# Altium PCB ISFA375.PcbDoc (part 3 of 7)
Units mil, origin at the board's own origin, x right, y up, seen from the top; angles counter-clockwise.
Board outline 5615 x 5520 mil, 6 copper layers (Top_SL, GND, POWER, Signal_Layer, GND2, Bottom_SL), stack 60.472 mil thick; 494 components, 307 nets, 1648 pads, 755 vias.
Unrouted connection lines stored in the file: 315.
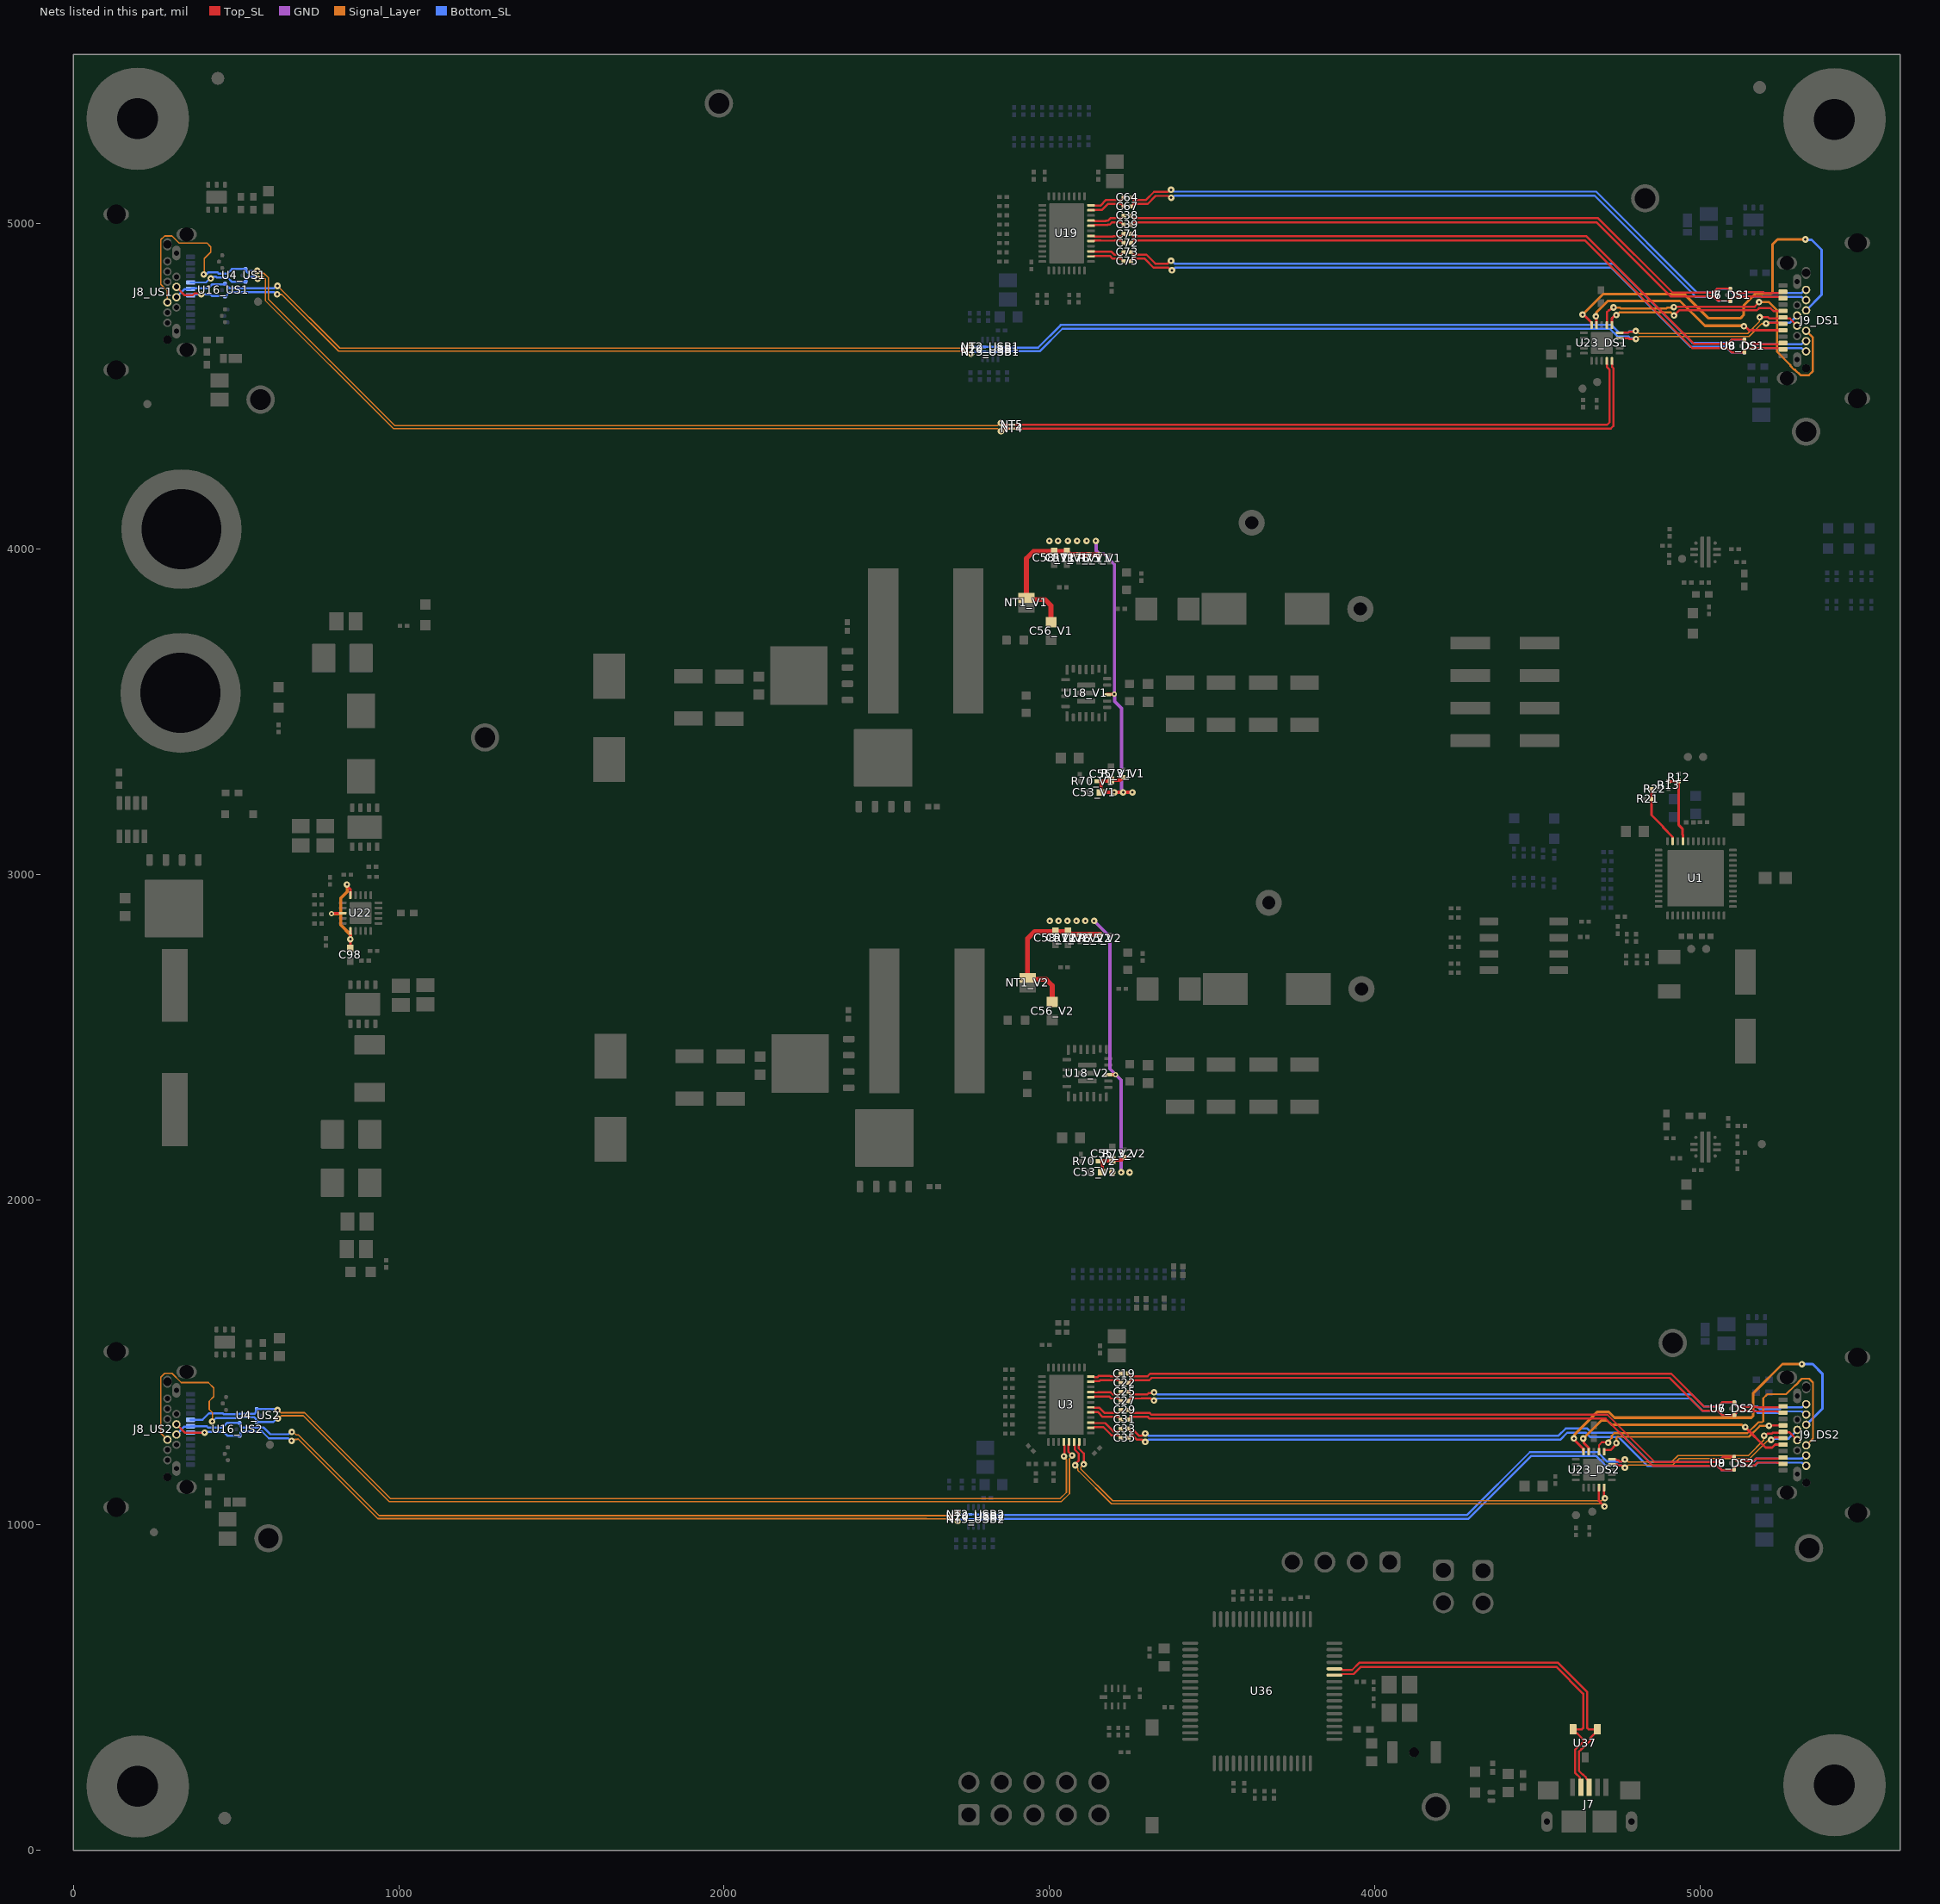
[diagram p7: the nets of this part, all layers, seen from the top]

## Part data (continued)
R114: library part CMP-0027444-1, "RES, 1.69 k, 1%, 0.05 W, 0201", Manufacturer="Yageo America", Power_W=50mW, Supplier Part Number 1=YAG2487CT-ND, TempCo="200 ppm/C", Tolerance_%=1%, Value2=0.05W, Value_Code=1k69, ValueDisplayed=1.69k
R115 R134: library part CMP-0027857-1, "RES, 715, 1%, 0.05 W, 0201", Manufacturer="Yageo America", Power_W=50mW, Supplier Part Number 1=YAG2786CT-ND, TempCo="200 ppm/C", Tolerance_%=1%, Value2=0.05W, Value_Code=715R, ValueDisplayed=715
R117_V1 R117_V2: library part CMP-0027696-1, "RES, 42.2 k, 1%, 0.05 W, 0201", Manufacturer="Yageo America", Power_W=50mW, Supplier Part Number 1=YAG2666CT-ND, TempCo="200 ppm/C", Tolerance_%=1%, Value2=0.05W, Value_Code=42k2, ValueDisplayed=42.2k
R127: library part CMP-0026825-5, "RES, 10 k, 5%, 0.063 W, AEC-Q200 Grade 0, 0402", Manufacturer=Vishay-Dale, Power_W=63mW, Supplier Part Number 1=541-10KJCT-ND, TempCo="200 ppm/C", Tolerance_%=5%, Value2=0.063W, Value_Code=10k0, ValueDisplayed=10k
R163_DS1 R163_DS2: library part CMP-0027261-3, "RES, 100 k, 1%, 0.05 W, 0201", Manufacturer=Vishay-Dale, Power_W=50mW, Supplier Part Number 1=541-100KAABCT-ND, TempCo="100 ppm/C", Tolerance_%=1%, Value2=0.05W, Value_Code=100k
R164 R172: library part CMP-0083836-1, "RES, 100, 1%, 0.05 W, 0201", Manufacturer=Vishay-Semiconductor, Power_W=50mW, TempCo="100 ppm/C", Tolerance_%=1%, Value2=0.05W, Value_Code=100R, ValueDisplayed=100
S1: library part CMP-0002163-2, "Switch, Slide, SPST, Top Slide, SMT", CurrentRating_mA=100A, Manufacturer="Copal Electronics", Supplier Part Number 1=563-1004-1-ND
S4: library part CMP-0095173-1, "Tactile Switch SPST-NO Top Actuated Surface Mount", Coil Resistance_ohm=100mΩ, Contact Current Rating=50mA, Digikey Part Number=SW1143CT-ND, Manufacturer=Omron, Mouser Part Number=653-B3U-1000P-B, Operating Force=1.5N, Operating Temperature Range="-25°C to +70°C"
TP1 TP2 TP4 TP5 TP13_DS1 TP13_DS2 TP14_DS1 TP14_DS2 TP15 TP16 TP17_US1 TP17_US2 TP18_US1 TP18_US2: library part CMP-0078143-3, "TEST POINT.  No entry in BOM.", Manufacturer=N/A
TP6 TP9_US1 TP9_US2 TP10_DS1 TP10_DS2 TP12 TP19: library part CMP-0055142-1, "Test Point, Compact, Red, TH", Color=Red, Manufacturer=Keystone, Supplier Part Number 1=36-5005-ND
TP7_V1 TP7_V2 TP8_V1 TP8_V2: library part CMP-0055140-1, "Test Point, Miniature, Orange, TH", Color=Orange, Manufacturer=Keystone, Supplier Part Number 1=36-5003-ND
TP11_DS1 TP11_DS2: library part CMP-0055143-2, "Test Point, Compact, Black, TH", Color=Black, Manufacturer="Keystone Electronics", Supplier Part Number 1=36-5006-ND
U1: library part CMP-0088521-10, "Dual Port USB Type-C and USB PD Controller with Integrated Source Power Switches", Manufacturer="Texas instruments", Max Supply Voltage=22V, Min Supply Voltage=0V, Operating Temperature Range="-10°C to +125°C"
U2: library part CMP-0005313-2, "256 kb I2C CMOS Serial EEPROM, SOIC-8", Manufacturer="ON Semiconductor", Supplier Part Number 1=CAT24C256WI-GT3OSCT-ND
U3: library part CMP-0082004-1, "USB TYPE-C(TM) 10 Gbps Multi-Protocol Bi-Directional Linear Redriver, RNQ0040A (WQFN-40)", Alternate Manufacturer="Texas Instruments", Alternate PartNumber=TUSB1044IRNQR, Operating Temperature Range="-40 to 85"
U4_US1 U4_US2 U6_DS1 U6_DS2 U7_DS1 U7_DS2 U8_DS1 U8_DS2 U9_DS1 U9_DS2 U12_US1 U12_US2 U13_US1 U13_US2 U14_US1 U14_US2 U15_US1 U15_US2 U16_US1 U16_US2: library part CMP-0013358-2, "2-Channel ESD Protection Diode for USB Type-C and HDMI 2.0, DMY0003A (X1SON-3)", Alternate Manufacturer="Texas Instruments"
U5: library part CMP-0091365-1, "Low IQ Reverse Battery Protection Controller, SOT23-8", Manufacturer="Texas Instruments", Max Supply Voltage=60V, Min Supply Voltage=4V, Nominal Supply Current=80uA, Operating Temperature Range="-40°C to +150°C"
U10 U25: library part CMP-0088339-1, "2.7- 23V, 5.5 A Integrated Ideal Diode Power Switch with Input Reverse Polarity and Overvoltage Protection", Manufacturer="Texas Instruments", Max Supply Voltage=23V, Min Supply Voltage=2.7V, Nominal Supply Current=230uA, Operating Temperature Range="-40°C to +125°C", Output Voltage=42V
U11: library part CMP-0033716-1, "High-Speed USB 2.0 (480 Mbps) 1:2 Multiplexer / Demultiplexer Switch with Single Enable, 6 ohm RON, 2.5 to 3.3V, -40 to 85 degC, 10-Pin UQFN (RSE), Green (RoHS & no Sb/Br)", Manufacturer="Texas Instruments"
U18_V1 U18_V2: library part CMP-0861085-2, "36-V, 16-A Buck-Boost Converter, RPM0026A (VQFN-HR-26)", Alternate Manufacturer="Texas Instruments"
U19: library part CMP-0092691-1, "USB Type-C 10Gbps USB3.2 x2 Adaptive Linear Redriver", Manufacturer="Texas Instruments", Max Supply Voltage=3.6V, Min Supply Voltage=1.7V, Operating Temperature Range="0°C to +70°C"
U20_USB1 U20_USB2: library part CMP-0093449-1, "USB 2.0 high-speed signal conditioner with BC 1.2 controller 12-X2QFN -40 to 85", Manufacturer="Texas Instruments", Max Supply Voltage=6.5V, Min Supply Voltage=2.3V, Mouser Part Number=595-TUSB216IRWBT, Nominal Supply Current=0.75-22mA, Operating Temperature Range="-40°C to +85°C"
U21_DS1 U21_DS2 U24_US1 U24_US2: library part CMP-0077834-1, "22-V Precision Surge Protection Clamp, DRV0006A (WSON-6)", Alternate Manufacturer="Texas Instruments"
U22: library part CMP-0081825-1, "Dual Synchronous Step-Down Controller with 5-V and 3.3-V LDOs, RUK0020B (WQFN-20)", Alternate Manufacturer="Texas Instruments", Alternate PartNumber=TPS51225RUKR, Operating Temperature Range="-40 to 85 C", Rating=Catalog
U23_DS1 U23_DS2: library part CMP-0081565-1, "USB Type-C Port Protector: Short-to-VBUS Overvoltage and IEC ESD Protection, RUK0020B (WQFN-20)", Alternate Manufacturer="Texas Instruments"
U36: library part CMP-0029860-3, "Tiva C Series Microcontroller, 256 KB Flash, 32 KB SRAM, 12 Bit, 12 Channels, -40 to 105 degC, 64-Pin LQFP (PM), Green (RoHS & no Sb/Br), Tape and Reel", Manufacturer="Texas Instruments", Temperature Range="-40 to 105 degC"
U37: library part CMP-0043101-1, "ESD Protection Array for High-Speed Data Interfaces, 2 Channels, -40 to +85 degC, 3-pin SOT-23 (DBZ), Green (RoHS & no Sb/Br)", Breakdown Voltage(Min)(V)=9, Differential Capacitance(pF)=0.01, IO Capacitance(Typ)(pF)=0.7, IO Leakage Current(nA)=10, Manufacturer="Texas Instruments"
Y1: library part CMP-0004635-3, "Crystal, 16 MHz, 8pF, SMD", Frequency Stability=+/-30ppm, Frequency_Fixed=16MHz, Manufacturer=NDK, Supplier Part Number 1=644-1157-1-ND

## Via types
v1: diameter 20, hole 8, Top_SL to Bottom_SL, 628 vias
v2: diameter 19.68, hole 7.87, Top_SL to Bottom_SL, 66 vias
v3: diameter 16, hole 8, Top_SL to Bottom_SL, 23 vias
v4: diameter 16, hole 6, Top_SL to Bottom_SL, tented both sides, 16 vias
v5: diameter 137.8, hole 125.98, Top_SL to Bottom_SL, 8 vias
v6: diameter 50, hole 28, Top_SL to Bottom_SL, 8 vias
v7: diameter 28, hole 16, Top_SL to Bottom_SL, 6 vias

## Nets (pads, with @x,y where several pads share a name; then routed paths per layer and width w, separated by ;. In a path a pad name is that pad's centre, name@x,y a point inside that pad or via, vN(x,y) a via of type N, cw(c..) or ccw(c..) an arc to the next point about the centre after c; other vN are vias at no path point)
3V3_LDO_EN: C98.1 U22.3 U22.6 U22.20 | length 340.7
  Top_SL w8: v3(792.61,2879.44) 793.36,2880.19 826.6,2880.19 U22.3@827.35,2880.95 ; v1(840.21,2968.87) 840.21,2965.62 851.04,2954.79 U22.20@850.98,2936.06 U22.20@850.98,2936.06 ; C98.1@850.16,2776.43 850.89,2777.16 850.89,2800.31 v1(851.22,2800.64) 851.1,2800.76 851.1,2825.71 U22.6@850.98,2825.83
  Signal_Layer w10: v3(792.61,2879.44) 821.45,2879.44 ; v1(840.21,2968.87) 841.3,2967.77 841.3,2946.86 821.45,2927.01 821.45,2879.44 ; v1(851.22,2800.64) 851.22,2814.76 821.45,2844.53 821.45,2879.44
ADCIN1: R12.2 R13.1 U1.33 | length 222.4
  Top_SL w8: R13.1@4903.32,3285.62 4933.62,3285.62 R12.2@4934.92,3286.92 ; R12.2@4934.92,3287.2 R12.2@4934.92,3286.92 ; U1.33@4947.63,3102.17 U1.33@4947.63,3102.17 4947.57,3121.23 4945.78,3123.01 4945.78,3140.48 4934.92,3151.34 R12.2@4934.92,3286.92
ADCIN2: R21.2 R22.1 U1.35 | length 187.2
  Top_SL w8: R22.1@4849.98,3262 4850.43,3261.55 4850.43,3232.01 R21.2@4850.88,3231.56 4850.88,3182.11 4886.5,3146.5 4886.5,3144.61 4916.07,3115.04 U1.35@4916.13,3102.17 U1.35@4916.13,3102.17
AGND_V1: C53_V1.2 C55_V1.1 C56_V1.2 C57_V1.2 C58_V1.2 NT1_V1.2 R70_V1.1 R73_V1.1 R75_V1.1 R76_V1.1 R117_V1.1 U18_V1.10 | length 1553.3
  Top_SL w10: R76_V1.1@3122.27,3982.39 R76_V1.1@3123.57,3983.69 ; R70_V1.1@3145.42,3285.96 3146.72,3287.26 3158.89,3287.26 ; C53_V1.2@3156.81,3252.17 C53_V1.2@3161.42,3252.17 ; U18_V1.10@3176.16,3553.74 v3(3199.63,3553.74) ; R73_V1.1@3226.92,3297.6 3218.66,3289.34 3189.99,3289.34 C55_V1.1@3189.63,3289.7 3187.19,3287.26 3158.89,3287.26 ; v1(3255.01,3252.17) v1(3226.85,3252.17) v1(3199.31,3252.17) C53_V1.2@3161.42,3252.17 ; 3158.89,3287.26 3158.89,3254.7 C53_V1.2@3161.42,3252.17
  Top_SL w15: C56_V1.2@3004.92,3775.56 3004.92,3826.39 2986.31,3845 2934.19,3845 NT1_V1.2@2929.19,3850 2929.19,3971 2950.76,3992.57 C58_V1.2@3014.74,3992.57 C57_V1.2@3053.74,3992.57 3062.54,3983.77 3089.37,3983.77 R76_V1.1@3122.27,3983.77 ; R76_V1.1@3122.27,3982.39 R75_V1.1@3152.39,3982.39
  GND w10: v1(3142.86,4025.35) 3144.02,4024.19 3144.02,3995.35 3154.34,3985.02 3168.09,3985.02 3199.63,3953.49 v3(3199.63,3553.74) 3200.78,3552.59 3200.78,3531.75 3221.67,3510.86 v1@3221.67,3252.17
  other v1: 2999.63,4025.35 3026.55,4025.35 3056.76,4025.35 3085,4025 3114,4025
AGND_V2: C53_V2.2 C55_V2.1 C56_V2.2 C57_V2.2 C58_V2.2 NT1_V2.2 R70_V2.1 R73_V2.1 R75_V2.1 R76_V2.1 R117_V2.1 U18_V2.10 | length 1446.7
  Top_SL w10: R70_V2.1@3149.2,2117.96 3150.5,2119.26 3162.67,2119.26 ; C53_V2.2@3165.21,2083.88 3165.21,2084.17 3162.67,2086.7 3162.67,2119.26 ; U18_V2.10@3181.12,2384.43 3181.19,2384.51 3203.18,2384.51 v3(3203.42,2384.75) ; R73_V2.1@3230.71,2129.6 3222.45,2121.34 3193.78,2121.34 C55_V2.1@3193.42,2121.7 3190.98,2119.26 3162.67,2119.26
  Top_SL w15: C56_V2.2@3008.71,2607.56 3008.71,2658.39 2990.09,2677 2937.98,2677 NT1_V2.2@2932.98,2682 2932.98,2803 2954.54,2824.57 C58_V2.2@3018.53,2824.57 C57_V2.2@3057.53,2824.57 3066.33,2815.77 R75_V2.1@3156.5,2815.77
  GND w10: v1(3137.18,2857.35) 3185.91,2808.61 3185.91,2402.25 v3(3203.42,2384.75) 3220.61,2367.56 v1(3220.61,2084.17)
  other v1: 3193.78,2083.88 3246.41,2083.88 3001,2857 3028,2857 3055.62,2857.35 3083,2857 3110.4,2857.29
AUX_DS1_N: NT5.2 U23_DS1.14 | length 2027.3
  Top_SL w6.5: NT5.2@2890.19,4381.81 2904,4381.81 4714.16,4381.81 4722.5,4390.16 4722.5,4550.85 4714.4,4558.96 4714.4,4577.36 U23_DS1.14@4713.72,4578.05
AUX_DS1_P: NT4.2 U23_DS1.15 | length 2048.7
  Top_SL w6.5: NT4.2@2889,4370 4724.66,4370.31 ; 4725.66,4370.31 4734,4378.66 4734,4555.62 4730.15,4559.47 4730.15,4577.36 U23_DS1.15@4729.46,4578.05
AUX_DS2_N: U3.26 U23_DS2.14 | length 1831.4
  Top_SL w6.5: U3.26@3075.86,1255.56 3076.55,1254.88 3076.55,1244.88 3078.05,1243.38 3078.05,1231.47 3090.46,1219.06 3090.46,1198.86 3079.17,1187.57 v1(3079.17,1183.91) ; U23_DS2.14@4689.43,1115.2 4689.43,1074.01 v1(4706.28,1057.15)
  Signal_Layer w4.32: v1(3079.17,1183.91) 3079.17,1181.99 3087.61,1173.54 3087.61,1168 3090.53,1165.07 3190.39,1065.21 4695.91,1065.21 4703.98,1057.15 v1(4706.28,1057.15)
AUX_DS2_P: U3.27 U23_DS2.15 | length 1783.2
  Top_SL w6.5: U3.27@3091.61,1255.56 3091.61,1247.69 3089.55,1245.63 3089.55,1236.23 3105.66,1220.12 v1(3105.66,1187.06) ; U23_DS2.15@4705.17,1115.2 4705.17,1084.61 v1(4707.68,1082.11)
  Signal_Layer w4.32: v1(3105.66,1187.06) 3105.66,1186.68 3096.93,1177.95 3096.93,1171.86 3194.25,1074.53 4697.3,1074.53 4704.88,1082.11 v1(4707.68,1082.11)
AUX_US1_N: J8_US1.B8 NT5.1 U4_US1.2@528.92,4860.69 | length 3205.7
  Top_SL w6.5: v1(2851.11,4387.78) 2854.76,4387.78 2860.73,4381.81 NT5.1@2879.81,4381.81
  Signal_Layer w4.32: J8_US1.B8@288.66,4758.5 288.66,4793.28 268.71,4813.23 268.71,4950.82 280.4,4962.51 302.59,4962.51 324.79,4940.32 410.49,4940.32 421.76,4929.04 421.76,4912.49 401.94,4892.67 401.94,4846.17 v1(400.2,4844.43) ; v1(565.27,4855.26) 568.65,4855.26 575.55,4848.35 584.51,4848.35 598.87,4833.99 598.87,4768.02 986.95,4379.94 2840.74,4379.94 2848.58,4387.78 v1(2851.11,4387.78)
  Bottom_SL w6.5: v1(400.2,4844.43) 402.79,4847.01 410.92,4847.01 414.21,4850.31 442.77,4850.31 445.83,4847.25 473.63,4847.25 487.07,4860.69 U4_US1.2@528.92,4860.69 531.14,4858.47 531.14,4853.82 535.38,4849.58 541.07,4855.26 v1(565.27,4855.26)
AUX_US1_P: J8_US1.A8 NT4.1 U4_US1.3@528.92,4821.32 | length 2790.7
  Top_SL w6.5: v1@2851,4363 2854.98,4363 2861.98,4370 NT4.1@2880,4370
  Signal_Layer w4.32: v1(565.6,4830.26) 566.78,4830.26 575.55,4839.03 580.65,4839.03 589.55,4830.13 589.55,4764.16 983.09,4370.62 2840.74,4370.62 2848.58,4362.78 v1(2851.11,4362.78)
  Bottom_SL w6.5: J8_US1.A8@359.92,4819.53 407.33,4819.53 416.43,4828.63 418.53,4828.63 v1(421.89,4831.99) ; v1@421.77,4832.06 425.42,4832.06 431.05,4837.69 437.71,4837.69 440.65,4834.75 473.63,4834.75 487.07,4821.32 U4_US1.3@528.92,4821.32 531.14,4823.53 531.14,4830.94 537.27,4837.08 555.65,4837.08 562.46,4830.26 v1(565.6,4830.26)
AUX_US2_N: J8_US2.B8 U3.25 U4_US2.2@562.87,1316.9 | length 3445.2
  Top_SL w6.5: U3.25@3060.11,1255.56 3060.11,1247.69 3058.05,1245.63 3058.05,1225.94 3069.67,1214.32 v1(3069.67,1214.04)
  Signal_Layer w4.32: J8_US2.B8@288.66,1262.5 268.71,1282.46 268.71,1454.82 280.4,1466.51 302.59,1466.51 331.16,1437.94 414.58,1437.94 431.34,1421.19 431.34,1395.01 417.19,1380.86 417.19,1355.28 427.24,1345.23 427.24,1319.62 v1(426.2,1318.58) ; v1(628.61,1327.9) 630.93,1327.9 639.02,1335.99 706.4,1335.99 969.97,1072.42 3037.34,1072.42 3061.56,1096.64 3061.56,1203.67 3069.67,1211.78 v1(3069.67,1214.04)
  Bottom_SL w6.5: v1(426.2,1318.58) 427.63,1318.58 437.71,1328.66 512.52,1328.66 514.69,1330.83 555.86,1330.83 561.19,1325.5 561.19,1318.58 U4_US2.2@562.87,1316.9 613.95,1316.9 624.96,1327.9 v1(628.61,1327.9)
AUX_US2_P: J8_US2.A8 U3.24 U4_US2.3@562.87,1356.27 | length 2986.8
  Top_SL w6.5: U3.24@3044.36,1255.56 3045.05,1254.88 3045.05,1244.88 3046.55,1243.38 3046.55,1222 3045.78,1221.23 3045.78,1212.42 v1(3044.8,1211.44)
  Signal_Layer w4.32: v1(627.45,1353.45) 629.71,1353.45 637.84,1345.31 710.26,1345.31 973.83,1081.74 3033.48,1081.74 3052.24,1100.5 3052.24,1201.07 3044.8,1208.5 v1(3044.8,1211.44)
  Bottom_SL w6.5: J8_US2.A8@359.92,1323.53 396.24,1323.53 416.05,1343.33 458.74,1343.33 461.92,1340.16 507.76,1340.16 509.93,1342.33 556.85,1342.33 560.65,1346.14 560.65,1354.05 U4_US2.3@562.87,1356.27 v1@620.98,1356.27
C_AUX_DS1_N: J9_DS1.B8 U23_DS1.2 | length 995.3
  Top_SL w6.5: U23_DS1.2@4713.72,4688.49 4713.72,4728.21 4719.44,4733.94 4721.58,4733.94 4730.35,4742.72 v1(4734,4742.72) ; v1(4919.2,4743.9) 4920.55,4745.25 5167.96,4745.25 v1(5181.54,4758.83)
  Signal_Layer w6.5: v1(4734,4742.72) 4734.25,4742.47 4753.75,4742.47 4757,4739.22 4896.2,4739.22 4899.45,4742.47 4917.77,4742.47 v1(4919.2,4743.9) ; v1(5181.54,4758.83) 5211.93,4758.83 5237.01,4733.75 5237.01,4606.53 5277.56,4565.97 5277.56,4563.63 5289.89,4551.3 5292.23,4551.3 5308.96,4534.57 5334.89,4534.57 5347.21,4546.9 5347.21,4649.73 J9_DS1.B8@5326.17,4670.77
C_AUX_DS1_P: J9_DS1.A8 U23_DS1.1 | length 563.7
  Top_SL w6.5: v1(4920.07,4717.75) 4936.07,4733.75 5174.71,4733.75 5181.54,4740.58 5217.09,4740.58 5225.87,4731.8 J9_DS1.A8@5254.91,4731.8
  Top_SL w8: U23_DS1.1@4729.53,4696.3 4729.53,4710.13 4731.7,4712.3 4732.55,4712.3 4739.57,4719.32 v1(4742.82,4719.32)
  Signal_Layer w6.5: v1(4742.82,4719.32) 4744.42,4719.32 4752.82,4727.72 4908.97,4727.72 4918.94,4717.75 v1(4920.07,4717.75)
C_AUX_DS2_N: J9_DS2.B8 U23_DS2.2 | length 1017.6
  Top_SL w6: U23_DS2.2@4689.43,1225.44 4689.43,1245.64 4698.23,1254.44 4716.05,1254.44 v1(4717.68,1252.81)
  Signal_Layer w6: v1(4717.68,1252.81) 4717.68,1256.6 4728.84,1267.76 4728.84,1274.5 4736.6,1282.25 5145.66,1282.25 5179.65,1316.23 5190.67,1316.23 5194.19,1319.75 5194.19,1389.37 5206.82,1402 5264.86,1402 5292.43,1429.58 ccw(c5279.27,1453.93) 5303.62,1440.76 5312.98,1450.12 5335.13,1450.12 5347.31,1437.94 5347.31,1266.06 J9_DS2.B8@5326.51,1245.27
C_AUX_DS2_P: J9_DS2.A8 U23_DS2.1 | length 597.7
  Top_SL w6.5: U23_DS2.1@4705.17,1225.44 4705.17,1229.56 4705.86,1230.25 4725.34,1230.25 4733.23,1238.14 4733.23,1238.94 4742.67,1248.38 v1(4742.67,1252.03) ; v1(5212.19,1305.23) 5212.71,1305.76 5254.72,1305.76 J9_DS2.A8@5255.25,1306.29
  Signal_Layer w6: v1(4742.67,1252.03) 4742.87,1252.23 4742.87,1267.74 4746.38,1271.25 5150.22,1271.25 5184.2,1305.23 v1(5212.19,1305.23)
C_CC1_DS1: J9_DS1.A5 U23_DS1.4 | length 666.5
  Top_SL w8: v1(4679.72,4715.3) 4681.28,4713.74 4681.28,4689.22 U23_DS1.4@4682.22,4688.29 ; v1(5134.9,4684.76) 5137.2,4682.46 5140.99,4682.46 5150.7,4672.74 J9_DS1.A5@5254.91,4672.74
  Signal_Layer w8: v1(4679.72,4715.3) 4681.94,4717.53 4681.94,4728.19 4716.66,4762.9 4938.58,4762.9 5014.96,4686.52 5133.14,4686.52 v1(5134.9,4684.76)
C_CC1_DS2: J9_DS2.A5 U23_DS2.4 | length 723.1
  Top_SL w8: v1(4641.13,1265.94) 4642.89,1264.18 4642.89,1252.59 4647.1,1248.38 4647.1,1248.19 4657.93,1237.36 U23_DS2.4@4657.93,1225.44 ; v1(5139,1301.04) 5201.91,1238.14 5221.65,1238.14 5230.75,1247.24 J9_DS2.A5@5255.25,1247.24
  Signal_Layer w8: v1(4641.13,1265.94) 4696.94,1321.75 4714.78,1321.75 4728.53,1308 5128.48,1308 5135.44,1301.04 v1(5139,1301.04)
C_CC2_DS1: J9_DS1.B5 U23_DS1.5 | length 1259.3
  Top_SL w8: v1(4639.1,4720.82) 4642.02,4720.82 4665.78,4697.05 4665.78,4688.97 U23_DS1.5@4666.47,4688.29
  Signal_Layer w8: v1(4639.1,4720.82) 4701.58,4783.3 4952.13,4783.3 5025.25,4710.17 5125.26,4710.17 5134.38,4719.29 5134.38,4748.68 5171.2,4785.5 5218.68,4785.5 5223.37,4790.19 5223.37,4937.12 5238.18,4951.93 v1(5323.71,4951.93)
  Bottom_SL w8: v1(5323.71,4951.93) 5325.1,4950.54 5343.46,4950.54 5373.92,4920.08 5373.92,4781.52 J9_DS1.B5@5326.17,4733.77
C_CC2_DS2: J9_DS2.B5 U23_DS2.5 | length 1162.6
  Top_SL w8: v1(4612.34,1266.06) 4612.34,1263.15 4641.24,1234.25 4641.24,1226.38 U23_DS2.5@4642.18,1225.44
  Signal_Layer w8: v1(4612.34,1266.06) 4614.64,1268.36 4614.64,1278.22 4683.87,1347.45 4719.86,1347.45 4737.23,1330.08 5158.31,1330.08 5163,1334.76 5163,1404.19 5253.52,1494.71 v1(5313.16,1494.71)
  Bottom_SL w8: v1(5313.16,1494.71) 5346.29,1494.71 5377,1464 5377,1358.75 J9_DS2.B5@5326.51,1308.26
CRX1_N: C73.2 U19.31 | length 108.7
  Top_SL w6.5: U19.31@3127.77,4915.33 3128.46,4914.64 3137.71,4914.64 3138.64,4913.7 3191.11,4913.7 3199.64,4905.17 3220.85,4905.17 3224.66,4908.98 3224.66,4909.87 3227.71,4912.92 C73.2@3228.5,4912.92
CRX1_P: C75.2 U19.30 | length 108.7
  Top_SL w6.5: U19.30@3127.77,4899.58 3128.46,4900.27 3137.71,4900.27 3138.64,4901.2 3185.93,4901.2 3194.47,4892.67 3220.85,4892.67 3224.66,4888.86 3224.66,4887.97 3227.71,4884.92 C75.2@3228.5,4884.92
CRX2_N: C39.2 U19.36 | length 108.9
  Top_SL w6.5: U19.36@3127.77,4994.07 3128.46,4994.76 3137.71,4994.76 3138.64,4995.69 3178.06,4995.69 3179.68,4997.32 3185.4,4997.32 3192.77,5004.69 3220.85,5004.69 3224.66,5000.88 3224.66,4999.97 3227.71,4996.92 C39.2@3228.5,4996.92
CRX2_P: C38.2 U19.37 | length 109.3
  Top_SL w6.5: U19.37@3127.77,5009.82 3128.46,5009.13 3137.71,5009.13 3138.64,5008.19 3172.88,5008.19 3174.5,5009.82 3180.22,5009.82 3187.59,5017.19 3221.28,5017.19 3225.08,5021 3225.08,5021.91 3228.13,5024.96 C38.2@3228.92,5024.96
CTX1_N: C74.2 U19.34 | length 105.5
  Top_SL w6.5: U19.34@3127.77,4962.57 3128.46,4961.89 3137.71,4961.89 3138.64,4960.95 3163.33,4960.95 3163.86,4960.42 3196.39,4960.42 3197.23,4961.25 3220.62,4961.25 3224.42,4965.06 3224.42,4965.95 3227.47,4969 C74.2@3228.26,4969
CTX1_P: C72.2 U19.33 | length 105.5
  Top_SL w6.5: U19.33@3127.77,4946.82 3128.46,4947.51 3137.71,4947.51 3138.64,4948.45 3158.16,4948.45 3158.69,4947.92 3201.57,4947.92 3202.4,4948.75 3220.64,4948.75 3224.45,4944.94 3224.45,4944.05 3227.5,4941 C72.2@3228.28,4941
CTX2_N: C67.2 U19.39 | length 112.9
  Top_SL w6.5: U19.39@3127.77,5041.31 3128.46,5042 3137.71,5042 3138.64,5042.94 3161.73,5042.94 3179.49,5060.71 3221.28,5060.71 3225.08,5056.9 3225.08,5056.01 3228.13,5052.96 C67.2@3228.92,5052.96
CTX2_P: C64.2 U19.40 | length 112.9
  Top_SL w6.5: U19.40@3127.77,5057.06 3128.46,5056.37 3137.71,5056.37 3138.64,5055.44 3156.55,5055.44 3174.32,5073.21 3221.28,5073.21 3225.08,5077.01 3225.08,5077.91 3228.13,5080.96 C64.2@3228.92,5080.96
D1_D_N: J9_DS1.A7 J9_DS1.B7 NT2_USB1.1 U20_USB1.1 U23_DS1.20 | length 2619.7
  Top_SL w6.5: U23_DS1.20@4753.09,4664.87 4779.34,4664.87 4782.59,4668.12 4799.9,4668.12 v1(4802.34,4670.55) ; v1(5183.63,4712.68) 5209.44,4712.68 5213.6,4708.52 5251.32,4708.52 J9_DS1.A7@5254.91,4712.11 5258.55,4708.47 5276.66,4708.47 J9_DS1.B7@5298.61,4686.52
  Signal_Layer w4.32: v1(4802.34,4670.55) 4804.88,4670.55 4812.71,4662.72 5014.62,4662.72 5014.77,4662.88 5146.7,4662.88 5182.73,4698.91 5182.73,4711.79 v1(5183.63,4712.68)
  Bottom_SL w6.5: 2817.08,4621.62 NT2_USB1.1@2821.08,4621.62 U20_USB1.1@2844.01,4621.62 2844.7,4620.93 2859.31,4620.93 2860.74,4619.49 2965.7,4619.49 3035.01,4688.8 4727.59,4688.8 4750.85,4665.54 4779.34,4665.54 4782.59,4668.79 4800.58,4668.79 v1(4802.34,4670.55)
D1_D_P: J9_DS1.A6 J9_DS1.B6 NT3_USB1.1 U20_USB1.2 U23_DS1.19 | length 2660.1
  Top_SL w6.5: U23_DS1.19@4753.09,4649.12 4753.77,4648.43 4779.34,4648.43 4782.22,4645.55 v1(4802.99,4645.55) ; v1(5203.09,4693.22) 5205.68,4695.8 5222.33,4695.8 5222.55,4696.02 5251.32,4696.02 J9_DS1.A6@5254.91,4692.43
  Signal_Layer w4.32: v1(4802.99,4645.55) 4804.91,4645.55 4812.76,4653.4 5018.48,4653.4 5018.63,4653.56 5150.56,4653.56 5189.32,4692.32 5202.2,4692.32 v1(5203.09,4693.22)
  Bottom_SL w6.5: 2817.08,4605.87 NT3_USB1.1@2821.08,4605.87 U20_USB1.2@2844.01,4605.87 2844.7,4606.55 2859.31,4606.55 2860.74,4607.99 2970.47,4607.99 3039.78,4677.3 4722.83,4677.3 4746.09,4654.04 4779.34,4654.04 4785.24,4648.13 4800.41,4648.13 v1(4802.99,4645.55) ; v1(5203.09,4693.22) 5205.45,4695.58 5276.17,4695.58 J9_DS1.B6@5298.61,4718.02
D1_D_USB2_N: J9_DS2.A7 J9_DS2.B7 NT2_USB2.1 U20_USB2.1 U23_DS2.20 | length 2728.3
  Top_SL w6.5: U23_DS2.20@4728.8,1201.82 4729.48,1201.13 4742.12,1201.13 4744.55,1198.7 4749.32,1198.7 4752.95,1195.06 4758.8,1195.06 4765.24,1201.5 v1(4768.9,1201.5) ; v1(5197.11,1274.56) 5200.77,1274.56 5207.28,1281.08 5220.4,1281.08 5223.16,1283.84 5252.49,1283.84 J9_DS2.A7@5255.25,1286.61 5256.34,1285.52 5274.45,1285.52 J9_DS2.B7@5298.95,1261.02
  Signal_Layer w4.32: v1(4768.9,1201.5) 4771.27,1201.5 4779.27,1193.5 4912.14,1193.5 4932.18,1213.55 5148.67,1213.55 5196.08,1260.96 5196.08,1273.53 v1(5197.11,1274.56)
  Bottom_SL w6.5: 2772.39,1032.55 NT2_USB2.1@2776.39,1032.55 2799.66,1032.55 U20_USB2.1@2800.02,1032.92 2800.71,1032.23 2815.31,1032.23 2816.75,1030.79 4283.7,1030.79 4477.11,1224.21 4685.27,1224.21 4714.88,1194.59 4758.34,1194.59 4765.25,1201.5 v1(4768.9,1201.5)
D1_D_USB2_P: J9_DS2.A6 J9_DS2.B6 NT3_USB2.1 U20_USB2.2 U23_DS2.19 | length 2757.3
  Top_SL w6.5: U23_DS2.19@4728.8,1186.07 4729.48,1186.76 4738.73,1186.76 4739.17,1187.2 4744.55,1187.2 4748.19,1183.56 4757.88,1183.56 4765.25,1176.18 v1(4768.9,1176.18) ; v1(5218.67,1261.9) 5221.24,1261.9 5229.03,1269.69 5252.49,1269.69 J9_DS2.A6@5255.25,1266.92
  Signal_Layer w4.32: v1(4768.9,1176.18) 4771.27,1176.18 4779.27,1184.18 4916,1184.18 4936.04,1204.23 5152.53,1204.23 5207.2,1258.9 5215.67,1258.9 v1(5218.67,1261.9)
  Bottom_SL w6.5: 2772.01,1017.17 NT3_USB2.1@2776.01,1017.17 U20_USB2.2@2800.02,1017.17 2800.71,1017.86 2815.31,1017.86 2816.75,1019.29 4288.46,1019.29 4481.87,1212.71 4680.5,1212.71 4710.11,1183.09 4758.34,1183.09 4765.25,1176.18 v1(4768.9,1176.18) ; v1(5218.67,1261.9) 5221.18,1264.41 5227.6,1264.41 5229.03,1265.83 5272.27,1265.83 J9_DS2.B6@5298.95,1292.51
D1_RX1_N: C73.1 J9_DS1.B10 U9_DS1.2@5136.46,4643.66 | length 2215.3
  Top_SL w6.5: C73.1@3250.54,4912.92 3251.33,4912.92 3254.38,4909.87 3254.38,4908.98 3258.19,4905.17 3298.01,4905.17 3325.66,4877.52 3363.44,4877.52 3371.73,4885.8 v1(3374,4885.8)
  Bottom_SL w6.5: v1(3374,4885.8) 3376.27,4885.8 3384.56,4877.52 4732.53,4877.52 4976.05,4634 5087.76,4634 5097.42,4643.66 U9_DS1.2@5136.46,4643.66 5138.68,4641.44 5138.68,4636.13 5144.93,4629.87 5312.82,4629.87 5322.22,4639.28 J9_DS1.B10@5326.17,4639.28
D1_RX1_P: C75.1 J9_DS1.B11 U9_DS1.3@5136.46,4604.29 | length 2218
  Top_SL w6.5: C75.1@3250.54,4884.92 3251.33,4884.92 3254.38,4887.97 3254.38,4888.86 3258.19,4892.67 3292.83,4892.67 3320.48,4865.02 3365.98,4865.02 3374.27,4856.74 v1(3376.54,4856.74)
  Bottom_SL w6.5: v1(3376.54,4856.74) 3378.82,4856.74 3387.1,4865.02 4727.35,4865.02 4970.87,4621.5 5080.21,4621.5 5097.42,4604.29 U9_DS1.3@5136.46,4604.29 5138.68,4606.51 5138.68,4611.47 5144.58,4617.37 5312.72,4617.37 5322.31,4607.78 J9_DS1.B11@5326.17,4607.78
D1_RX2_N: C39.1 J9_DS1.A10 U6_DS1.2@5093.17,4761.33 | length 2121
  Top_SL w6.5: C39.1@3250.54,4996.92 3251.33,4996.92 3254.38,4999.97 3254.38,5000.88 3258.19,5004.69 4681.48,5004.69 4910.24,4775.93 5042.11,4775.93 5054.5,4763.54 5090.95,4763.54 U6_DS1.2@5093.17,4761.33 5095.39,4763.54 5095.39,4768.86 5101.29,4774.76 5143.9,4774.76 5146.22,4777.08 5189.29,4777.08 5191.61,4774.76 5251.32,4774.76 J9_DS1.A10@5254.91,4771.17
D1_RX2_P: C38.1 J9_DS1.A11 U6_DS1.3@5093.17,4800.7 | length 2120.4
  Top_SL w6.5: C38.1@3250.97,5024.96 3251.76,5024.96 3254.8,5021.91 3254.8,5021 3258.61,5017.19 4686.66,5017.19 4915.41,4788.43 5040.92,4788.43 5053.51,4801.03 5081.39,4801.03 5082.31,4800.12 5092.59,4800.12 U6_DS1.3@5093.17,4800.7 5095.39,4798.48 5095.39,4793.16 5101.29,4787.26 5138.72,4787.26 5141.04,4789.58 5194.47,4789.58 5196.79,4787.26 5251.32,4787.26 J9_DS1.A11@5254.91,4790.85
D1_TX1_N: C74.1 J9_DS1.A3 U8_DS1.3@5136.75,4643.95 | length 2161.5
  Top_SL w6.5: C74.1@3250.31,4969 3251.09,4969 3254.14,4965.95 3254.14,4965.06 3257.95,4961.25 4650.75,4961.25 4981.66,4630.35 5084.11,4630.35 5097.72,4643.95 U8_DS1.3@5136.75,4643.95 5138.97,4641.74 5138.97,4636.42 5144.87,4630.52 5187.95,4630.52 5188.69,4629.78 5251.32,4629.78 J9_DS1.A3@5254.91,4633.37
D1_TX1_P: C72.1 J9_DS1.A2 U8_DS1.2@5136.75,4604.59 | length 2161.3
  Top_SL w6.5: C72.1@3250.33,4941 3251.12,4941 3254.17,4944.05 3254.17,4944.94 3257.97,4948.75 4645.58,4948.75 4976.48,4617.85 5083.86,4617.85 5097.13,4604.59 U8_DS1.2@5136.75,4604.59 5138.97,4606.8 5138.97,4612.12 5144.87,4618.02 5182.77,4618.02 5183.51,4617.28 5251.32,4617.28 J9_DS1.A2@5254.91,4613.69
D1_TX2_N: C67.1 J9_DS1.B3 U7_DS1.3@5093.26,4761.29 | length 2244.8
  Top_SL w6.5: C67.1@3250.97,5052.96 3251.76,5052.96 3254.8,5056.01 3254.8,5056.9 3258.61,5060.71 3301.9,5060.71 3326.76,5085.56 3364.96,5085.56 3370.84,5079.68 v1(3374.49,5079.68)
  Bottom_SL w6.5: v1(3374.49,5079.68) 3378.15,5079.68 3384.76,5086.3 4675.8,5086.3 4986.53,4775.57 5042.48,4775.57 5056.75,4761.29 U7_DS1.3@5093.26,4761.29 5095.48,4763.51 5095.48,4770.92 5099.29,4774.73 5143.95,4774.73 5146.31,4777.08 5189.66,4777.08 5191.98,4774.76 5312.82,4774.76 5322.31,4765.26 J9_DS1.B3@5326.17,4765.26
D1_TX2_P: C64.1 J9_DS1.B2 U7_DS1.2@5093.26,4800.66 | length 2244.1
  Top_SL w6.5: C64.1@3250.97,5080.96 3251.76,5080.96 3254.8,5077.91 3254.8,5077.01 3258.61,5073.21 3296.72,5073.21 3321.58,5098.06 3363.73,5098.06 3370.35,5104.68 v1(3374,5104.68)
  Bottom_SL w6.5: v1(3374,5104.68) 3377.65,5104.68 3383.53,5098.8 4680.98,5098.8 4991.71,4788.07 5041.29,4788.07 5053.88,4800.66 U7_DS1.2@5093.26,4800.66 5095.48,4798.44 5095.48,4791.03 5099.29,4787.23 5138.78,4787.23 5141.13,4789.58 5194.83,4789.58 5197.15,4787.26 5312.82,4787.26 5322.31,4796.76 J9_DS1.B2@5326.17,4796.76
D2_RX1_N: C33.1 J9_DS2.B10 U9_DS2.2@5104.92,1209.68 | length 2171.4
  Top_SL w6.5: C33.1@3242.11,1296.29 3242.9,1296.29 3245.95,1293.24 3245.95,1292.05 3249.75,1288.24 3261.34,1288.24 3274.85,1274.73 3284.32,1274.73 3290.95,1281.36 v1(3294.6,1281.36)
  Bottom_SL w6.5: v1(3294.6,1281.36) 3298.25,1281.36 3304.91,1274.7 4564.82,1274.7 4586.93,1296.81 4653.74,1296.81 4667.06,1283.5 4710.99,1283.5 4711.05,1283.56 4754.63,1283.56 4844.28,1193.91 5055.03,1193.91 5070.81,1209.68 U9_DS2.2@5104.92,1209.68 5107.14,1207.47 5107.14,1206.4 5117.29,1196.25 5165.51,1196.25 5173.53,1204.27 5313.16,1204.27 5322.66,1213.77 J9_DS2.B10@5326.51,1213.77
D2_RX1_P: C35.1 J9_DS2.B11 U9_DS2.3@5104.92,1170.32 | length 2172.5
  Top_SL w6.5: C35.1@3242.11,1267.69 3242.9,1267.69 3246.97,1271.76 3246.97,1271.93 3250.78,1275.74 3256.16,1275.74 3269.67,1262.23 3284.27,1262.23 3290.93,1255.57 v1(3294.58,1255.57)
  Bottom_SL w6.5: v1(3294.58,1255.57) 3298.23,1255.57 3304.86,1262.2 4570,1262.2 4592.11,1284.31 4648.57,1284.31 4661.88,1271 4716.17,1271 4716.23,1271.06 4749.45,1271.06 4839.1,1181.41 5053.85,1181.41 5066.44,1168.82 5103.42,1168.82 5107.14,1172.53 5107.14,1177.85 5113.04,1183.75 5170.68,1183.75 5178.71,1191.77 5313.16,1191.77 5322.66,1182.28 J9_DS2.B11@5326.51,1182.28
D2_RX2_N: C22.1 J9_DS2.A10 U6_DS2.2@5105.39,1337.82 | length 2078
  Top_SL w6.5: C22.1@3242.11,1437.29 3242.9,1437.29 3245.95,1440.34 3245.95,1441.39 3249.75,1445.2 3306.98,1445.2 3314.29,1452.51 4906.36,1452.51 5007.54,1351.33 5055.16,1351.33 5068.66,1337.82 U6_DS2.2@5105.39,1337.82 5105.39,1338.2 5110.7,1343.51 5110.7,1347.45 5114.51,1351.25 5167.13,1351.25 5169.13,1349.25 5238.06,1349.25 5238.1,1349.21 5251.71,1349.21 J9_DS2.A10@5255.25,1345.66
D2_RX2_P: C19.1 J9_DS2.A11 U6_DS2.3@5105.39,1377.19 | length 2078.3
  Top_SL w6.5: C19.1@3241.75,1465.61 3242.54,1465.61 3245.58,1462.56 3245.58,1461.51 3249.39,1457.7 3301.8,1457.7 3309.11,1465.01 4911.54,1465.01 5012.72,1363.83 5055.05,1363.83 5068.42,1377.19 U6_DS2.3@5105.39,1377.19 5105.39,1376.81 5110.7,1371.49 5110.7,1367.56 5114.51,1363.75 5172.31,1363.75 5174.31,1361.75 5238.06,1361.75 5238.1,1361.8 5251.71,1361.8 J9_DS2.A11@5255.25,1365.35
D2_TX1_N: C29.1 J9_DS2.A3 U8_DS2.3@5104.92,1209.68 | length 2100
  Top_SL w6.5: C29.1@3242.11,1353.29 3242.9,1353.29 3245.95,1350.24 3245.95,1348.85 3249.75,1345.04 3307.94,1345.04 3313.46,1339.51 4715.31,1339.51 4860.91,1193.91 5055.03,1193.91 5070.81,1209.68 U8_DS2.3@5104.92,1209.68 5107.14,1207.47 5107.14,1202.15 5113.04,1196.25 5163.38,1196.25 5171.41,1204.27 5238.06,1204.27 5238.1,1204.32 5251.71,1204.32 J9_DS2.A3@5255.25,1207.87
D2_TX1_P: C31.1 J9_DS2.A2 U8_DS2.2@5104.92,1170.32 | length 2099.3
  Top_SL w6.5: C31.1@3242.11,1324.29 3242.9,1324.29 3245.95,1327.34 3245.95,1328.73 3249.75,1332.54 3302.76,1332.54 3308.29,1327.01 4710.14,1327.01 4855.74,1181.41 5053.85,1181.41 5066.44,1168.82 5103.42,1168.82 U8_DS2.2@5104.92,1170.32 5107.14,1172.53 5107.14,1177.85 5113.04,1183.75 5168.56,1183.75 5176.59,1191.77 5238.06,1191.77 5238.1,1191.73 5251.71,1191.73 J9_DS2.A2@5255.25,1188.18
D2_TX2_N: C27.1 J9_DS2.B3 U7_DS2.3@5105.92,1338.32 | length 2132.2
  Top_SL w6.5: C27.1@3242.11,1381.29 3242.9,1381.29 3245.95,1384.34 3245.95,1385.23 3249.75,1389.04 3283.53,1389.04 3283.64,1389.15 3311.52,1389.15 3317.91,1382.76 v1(3321.56,1382.76)
  Bottom_SL w6.5: v1(3321.56,1382.76) 3325.21,1382.76 3331.43,1388.97 4969.89,1388.97 5007.33,1351.53 5054.95,1351.53 5068.17,1338.32 U7_DS2.3@5105.92,1338.32 5108.14,1340.53 5108.14,1345.85 5114.04,1351.75 5170.49,1351.75 5177.99,1344.25 5251.06,1344.25 5256.06,1349.25 5313.16,1349.25 5322.66,1339.76 J9_DS2.B3@5326.51,1339.76
D2_TX2_P: C25.1 J9_DS2.B2 U7_DS2.2@5105.92,1377.68 | length 2132.4
  Top_SL w6.5: C25.1@3242.11,1409.29 3242.9,1409.29 3245.95,1406.24 3245.95,1405.35 3249.75,1401.54 3278.35,1401.54 3278.46,1401.65 3300.93,1401.65 3304.71,1405.43 3319.23,1405.43 v1(3321.7,1407.89)
  Bottom_SL w6.5: v1(3321.7,1407.89) 3325.35,1407.89 3331.78,1401.47 4975.07,1401.47 5012.51,1364.03 5055.26,1364.03 5068.91,1377.68 U7_DS2.2@5105.92,1377.68 5108.14,1375.47 5108.14,1370.15 5114.04,1364.25 5175.67,1364.25 5183.17,1356.75 5245.88,1356.75 5250.88,1361.75 5313.16,1361.75 5322.66,1371.25 J9_DS2.B2@5326.51,1371.25
D_US1_N: J8_US1.A7 J8_US1.B7 NT2_USB1.2 U16_US1.2@465.84,4815.69 U20_USB1.8 | length 2611.3
  Signal_Layer w4.32: v1(627,4809) 818.56,4617.44 2751.53,4617.44 v1(2759.65,4625.55)
  Bottom_SL w6.5: J8_US1.B7@316.22,4774.25 340.72,4798.75 358.83,4798.75 362.27,4802.19 414.48,4802.19 426.44,4814.15 U16_US1.2@467,4814.15 ; U16_US1.2@465.84,4815.69 479.34,4802.19 616.54,4802.19 623.35,4809 v1(627,4809) ; v1(2759.65,4625.55) 2763.3,4625.55 2767.24,4621.62 U20_USB1.8@2792.83,4621.62 NT2_USB1.2@2817.08,4621.62
D_US1_P: J8_US1.A6 J8_US1.B6 NT3_USB1.2 U16_US1.3@465.84,4776.32 U20_USB1.7 | length 2636.7
  Top_SL w6.5: J8_US1.B6@316.22,4805.75 341.81,4780.16 365.66,4780.16 371.36,4785.86 390.69,4785.86 v1(393.28,4783.28)
  Signal_Layer w4.32: v1(626.27,4783.13) 626.8,4782.6 640.22,4782.6 814.7,4608.12 2747.88,4608.12 v1@2757.5,4598.5
  Bottom_SL w6.5: J8_US1.A6@359.92,4780.16 362.9,4783.13 v1@393.13,4783.13 ; v1@393.42,4783.13 393.56,4783.28 420.81,4783.28 426.44,4777.65 467.18,4777.65 479.22,4789.69 616.06,4789.69 622.62,4783.13 v1(626.27,4783.13) ; v1(2759,4600) 2762.65,4600 2768.52,4605.87 U20_USB1.7@2792.83,4605.87 NT3_USB1.2@2817.08,4605.87
D_US2_N: J8_US2.A7 J8_US2.B7 NT2_USB2.2 U16_US2.2@510.47,1313.68 U20_USB2.8 | length 2607.5
  Signal_Layer w4.32: v1(671,1286) 675.24,1286 684.35,1276.89 691.29,1276.89 939.03,1029.14 2626.76,1029.14 2627.05,1028.86 2707.13,1028.86 2715.13,1036.86 v1(2717.5,1036.86)
  Bottom_SL w6.5: J8_US2.B7@316.22,1278.25 340.72,1302.75 358.83,1302.75 J8_US2.A7@359.92,1303.84 409.47,1303.84 413.92,1299.4 457.37,1299.4 471.66,1313.68 U16_US2.2@510.47,1313.68 512.69,1311.47 512.69,1304.06 516.5,1300.25 584.46,1300.25 605.6,1279.11 660.45,1279.11 667.35,1286 v1(671,1286) ; v1(2717.5,1036.86) 2721.15,1036.86 2725.09,1032.92 U20_USB2.8@2748.84,1032.92 NT2_USB2.2@2772.39,1032.92
D_US2_P: J8_US2.A6 J8_US2.B6 NT3_USB2.2 U16_US2.3@510.47,1274.31 U20_USB2.7 | length 2647.5
  Top_SL w6.5: J8_US2.B6@316.22,1309.75 341.81,1284.16 403.03,1284.16 v1(403.19,1284.32)
  Signal_Layer w4.32: v1(670.54,1259.2) 674.78,1259.2 678.7,1263.12 687.56,1263.12 689.72,1265.28 935.17,1019.83 2622.24,1019.83 2622.53,1019.54 2708.08,1019.54 2715.75,1011.87 v1(2718.45,1011.87)
  Bottom_SL w6.5: J8_US2.A6@359.92,1284.16 360,1284.24 403.11,1284.24 v1(403.19,1284.32) 405.77,1286.9 461.13,1286.9 473.71,1274.31 U16_US2.3@510.47,1274.31 512.69,1276.53 512.69,1283.94 516.5,1287.75 579.28,1287.75 600.42,1266.61 659.98,1266.61 667.39,1259.2 v1(670.54,1259.2) ; v1(2718.45,1011.87) 2721.68,1011.87 2726.98,1017.17 U20_USB2.7@2748.84,1017.17 NT3_USB2.2@2772.01,1017.17
DRX1_N: C33.2 U3.31 | length 108
  Top_SL w6.5: U3.31@3127.04,1314.62 3127.73,1313.93 3136.97,1313.93 3137.41,1313.5 3171.07,1313.5 3196.33,1288.24 3212.42,1288.24 3216.23,1292.05 3216.23,1293.24 3219.28,1296.29 C33.2@3220.06,1296.29
DRX1_P: C35.2 U3.30 | length 108.4
  Top_SL w6.5: U3.30@3127.04,1298.87 3134.91,1298.87 3137.04,1301 3165.89,1301 3191.15,1275.74 3212.42,1275.74 3216.23,1271.93 3216.23,1270.74 3219.28,1267.69 C35.2@3220.06,1267.69
DRX2_N: C22.2 U3.39 | length 99.2
  Top_SL w6.5: U3.39@3127.04,1440.6 3127.73,1441.29 3136.97,1441.29 3137.91,1442.23 3153.11,1442.23 3156.49,1445.61 3181.73,1445.61 3182.14,1445.2 3212.42,1445.2 3216.23,1441.39 3216.23,1440.34 3219.28,1437.29 C22.2@3220.06,1437.29
DRX2_P: C19.2 U3.40 | length 98.8
  Top_SL w6.5: U3.40@3127.04,1456.35 3127.73,1455.66 3136.97,1455.66 3137.91,1454.73 3147.93,1454.73 3151.31,1458.11 3186.91,1458.11 3187.32,1457.7 3212.06,1457.7 3215.86,1461.51 3215.86,1462.56 3218.91,1465.61 C19.2@3219.7,1465.61
DTX1_N: C29.2 U3.34 | length 104.2
  Top_SL w6.5: U3.34@3127.04,1361.86 3127.73,1361.18 3136.97,1361.18 3137.91,1360.24 3153.99,1360.24 3169.19,1345.04 3212.42,1345.04 3216.23,1348.85 3216.23,1350.24 3219.28,1353.29 C29.2@3220.06,1353.29
DTX1_P: C31.2 U3.33 | length 104.2
  Top_SL w6.5: U3.33@3127.04,1346.12 3127.73,1346.8 3136.97,1346.8 3137.91,1347.74 3148.81,1347.74 3164.01,1332.54 3212.42,1332.54 3216.23,1328.73 3216.23,1327.34 3219.28,1324.29 C31.2@3220.06,1324.29
DTX2_N: C27.2 U3.36 | length 100.3
  Top_SL w6.5: U3.36@3127.04,1393.36 3127.73,1394.05 3136.97,1394.05 3137.91,1394.98 3154.74,1394.98 3155.24,1395.48 3182.91,1395.48 3189.36,1389.04 3212.42,1389.04 3216.23,1385.23 3216.23,1384.34 3219.28,1381.29 C27.2@3220.06,1381.29
DTX2_P: C25.2 U3.37 | length 100.3
  Top_SL w6.5: U3.37@3127.04,1409.11 3127.73,1408.42 3136.97,1408.42 3137.91,1407.48 3149.57,1407.48 3150.07,1407.98 3188.09,1407.98 3194.54,1401.54 3212.42,1401.54 3216.23,1405.35 3216.23,1406.24 3219.28,1409.29 C25.2@3220.06,1409.29
F_USB_D_N: J7.2 U36.43 U37.2 | length 1162.1
  Top_SL w6.5: U36.43@3875.82,538.41 3896.41,538.41 3900,542 3935.62,542 3957.76,564.14 4558.13,564.14 4640.85,481.41 4640.85,376.23 4637.04,372.42 U37.2@4609.7,372.42 4609.7,367.5 4617.28,359.92 4622.2,359.92 4642.22,339.9 4642.22,334.51 4630.85,323.14 4629.65,323.14 4615.53,309.01 4615.53,239.34 4630.7,224.17 4630.7,196.89 J7.2@4633.73,193.86
F_USB_D_P: J7.3 U36.44 U37.1 | length 1184.9
  Top_SL w6.5: U36.44@3875.82,558.09 3896.41,558.09 3900,554.5 3930.44,554.5 3952.58,576.64 4563.3,576.64 4653.35,486.59 4653.35,376.23 4657.16,372.42 4660.57,372.42 U37.1@4684.5,372.42 4684.5,367.5 4662.78,345.78 4662.78,337.39 4636.02,310.64 4634.83,310.64 4628.03,303.83 4628.03,244.52 4639.59,232.96 4640.75,232.96 4649.85,223.85 4649.85,222.03 4659.32,212.56 J7.3@4659.32,193.86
